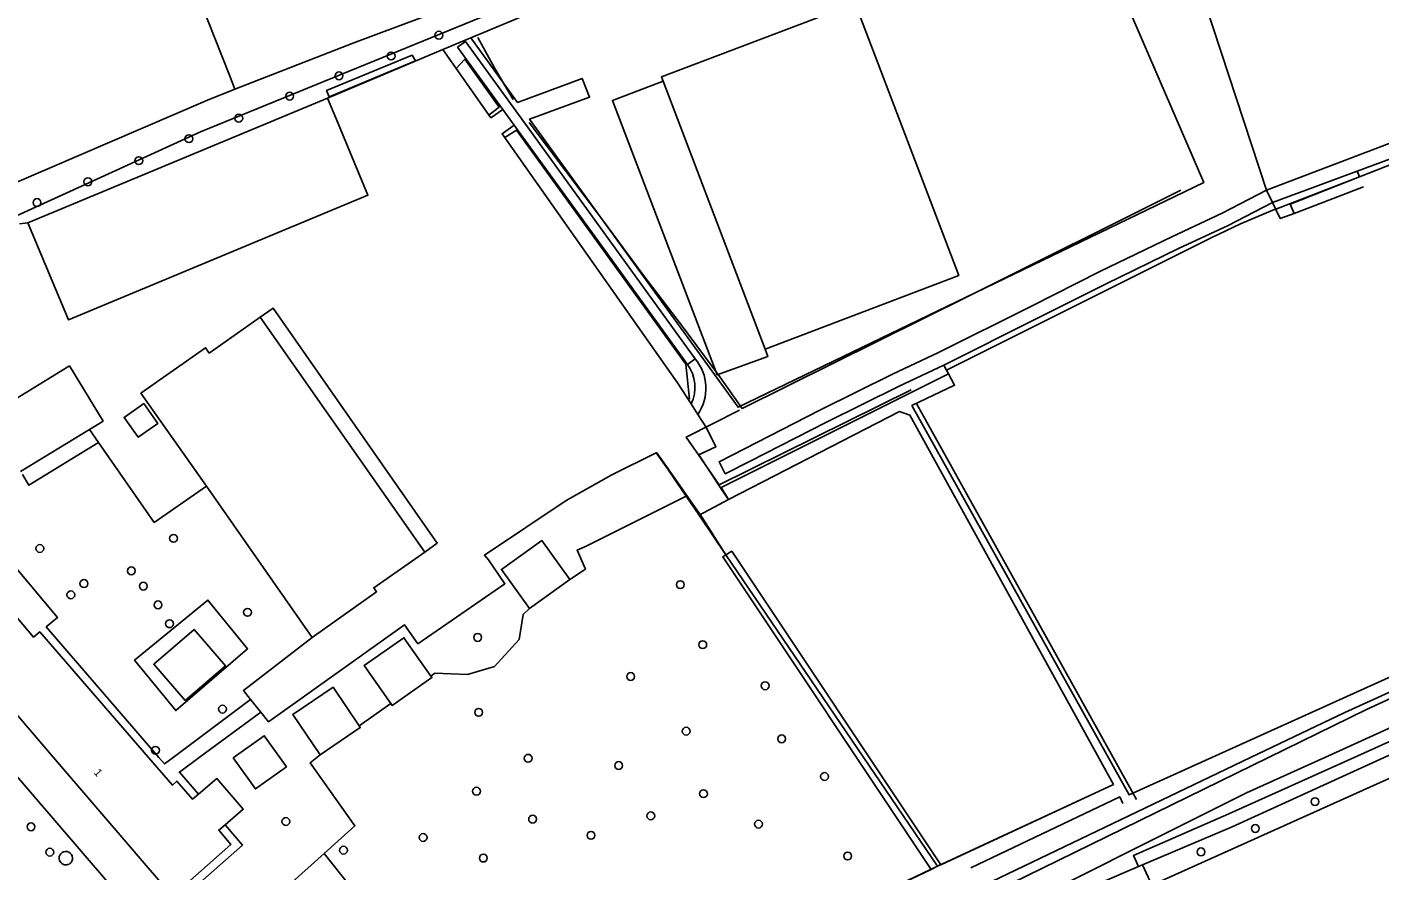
# Model space of a CAD drawing. Extents: x 160203 to 161526, y 379529 to 381797.
# Drawn here: x 161056.6 to 161225.7, y 381235.8 to 381341.3 of the extents above; entities that cross this region are included whole.
import ezdxf

# ---------------------------------------------------------------- set-up
doc = ezdxf.new("R2010")
doc.units = 0
for name, color, linetype in [('IMGEO_Boom', 7, 'Continuous'), ('IMGEO_Bouwland', 7, 'Continuous'), ('IMGEO_Erf', 7, 'Continuous'), ('IMGEO_Grasland_agrarisch', 7, 'Continuous'), ('IMGEO_Grasland_overig', 7, 'Continuous'), ('IMGEO_Groenvoorziening', 7, 'Continuous'), ('IMGEO_Haag', 7, 'Continuous'), ('IMGEO_Hek', 7, 'Continuous'), ('IMGEO_Loofbos', 7, 'Continuous'), ('IMGEO_Open_loods', 7, 'Continuous'), ('IMGEO_Opslagtank', 7, 'Continuous'), ('IMGEO_Pand', 7, 'Continuous'), ('IMGEO_Pand_nummerreeks', 7, 'Continuous'), ('IMGEO_Pand_vergunning_verleend', 7, 'Continuous'), ('IMGEO_Rijbaan_lokaal_gesloten', 7, 'Continuous'), ('IMGEO_Rijbaan_lokaal_halfverhard', 7, 'Continuous'), ('IMGEO_Rijbaan_lokaal_open', 7, 'Continuous'), ('IMGEO_Terreindeel_open', 7, 'Continuous'), ('IMGEO_Voetpad_onverhard', 7, 'Continuous'), ('IMGEO_Waterloop', 7, 'Continuous')]:
    doc.layers.add(name, color=color, linetype=linetype)

msp = doc.modelspace()

# ---------------------------------------------------------------- linework, layer by layer
at = {"layer": 'IMGEO_Boom'}
for centre in [(161108.08, 381340.25), (161102.12, 381337.65), (161095.61, 381335.18), (161089.44, 381332.64), (161083.08, 381329.88), (161076.85, 381327.32), (161070.59, 381324.57), (161064.23, 381321.94), (161057.87, 381319.34), (161074.93, 381277.38), (161058.22, 381276.11), (161069.65, 381273.32), (161063.73, 381271.73), (161071.16, 381271.41), (161138.26, 381271.6), (161062.1, 381270.32), (161072.99, 381269.07), (161084.18, 381268.14), (161074.43, 381266.71), (161112.94, 381265), (161141.06, 381264.09), (161132.05, 381260.11), (161148.86, 381258.96), (161081.05, 381256.04), (161113.06, 381255.64), (161138.99, 381253.28), (161150.93, 381252.33), (161072.67, 381250.89), (161119.24, 381249.9), (161130.55, 381248.99), (161156.28, 381247.62), (161112.79, 381245.78), (161141.15, 381245.47), (161217.57, 381244.48), (161088.97, 381242), (161119.8, 381242.29), (161134.57, 381242.7), (161148.03, 381241.67), (161057.12, 381241.34), (161106.12, 381240), (161127.1, 381240.27), (161210.12, 381241.13), (161096.17, 381238.41), (161059.47, 381238.16), (161113.64, 381237.43), (161159.17, 381237.69), (161203.32, 381238.2)]:
    msp.add_circle(centre, 0.489, dxfattribs=at)
at = {"layer": 'IMGEO_Bouwland'}
for points in [[(161112.08, 381339.93), (161123.08, 381344.5), (161184.52, 381366.19)], [(161184.52, 381366.19), (161203.67, 381321.85), (161145.48, 381293.77), (161119.43, 381329.78), (161126.93, 381332.52), (161125.99, 381334.85), (161117.92, 381331.86), (161112.08, 381339.93)], [(161136.11, 381334.49), (161129.77, 381332.1), (161142.87, 381297.82), (161149.18, 381300.1), (161148.85, 381301.02)]]:
    msp.add_lwpolyline(points, dxfattribs=at)
at = {"layer": 'IMGEO_Erf'}
for points in [[(161065.57, 381289.34), (161072.53, 381279.38), (161079.03, 381283.91)], [(161084.55, 381257.25), (161074.88, 381250), (161073.81, 381249.19), (161073.11, 381250), (161059.03, 381266.32), (161060.41, 381267.49), (161053.4, 381275.9), (161052.82, 381276.6)], [(161092.25, 381265), (161083.66, 381258.35), (161084.55, 381257.25)], [(161084.55, 381257.25), (161085.82, 381255.66)]]:
    msp.add_lwpolyline(points, dxfattribs=at)
at = {"layer": 'IMGEO_Grasland_agrarisch'}
for points in [[(161300.42, 381292.52), (161377.22, 381326.32), (161379.59, 381328.48), (161381.46, 381331.14), (161382.56, 381334.21), (161382.85, 381337.29), (161360.06, 381376.34), (161223.13, 381322.55)], [(161171.51, 381298.41), (161204.59, 381314.93), (161208.28, 381316.67), (161212.29, 381318.38), (161212.66, 381318.52), (161223.13, 381322.55)], [(161171.79, 381297.92), (161171.51, 381298.41)], [(161124.44, 381272.23), (161126.4, 381273.53), (161125.38, 381275.91), (161126.59, 381276.43), (161138.99, 381282.66)], [(161138.99, 381282.66), (161140.6, 381280.28)], [(161140.6, 381280.28), (161144.26, 381282.23)], [(161140.6, 381280.28), (161143.96, 381275.34)], [(161107.07, 381260.17), (161107.58, 381260.53), (161111.67, 381260.36), (161115.03, 381261.35), (161118.13, 381264.76), (161118.64, 381267.85), (161119.41, 381268.62)], [(161098.13, 381253.95), (161102.09, 381256.74)], [(161093.77, 381238.02), (161097.59, 381241.44), (161092, 381249.32), (161093.26, 381250.34)], [(161079.94, 381192.47), (161084.34, 381200.96), (161079.74, 381206.3), (161075.58, 381212.66), (161074.91, 381214.56), (161075.03, 381217.51), (161076.07, 381220.93), (161076.55, 381222.59), (161093.77, 381238.02)], [(161100.9, 381232.41), (161097.9, 381232.77), (161093.77, 381238.02)]]:
    msp.add_lwpolyline(points, dxfattribs=at)
at = {"layer": 'IMGEO_Grasland_overig'}
for points in [[(161367.83, 381310.71), (161294.02, 381278.51), (161294.05, 381277.58), (161293.85, 381277.49), (161232.69, 381250), (161197.17, 381234.04)], [(161143.29, 381283.7), (161171.79, 381297.92)], [(161171.79, 381297.92), (161172.53, 381296.53), (161167.2, 381293.97), (161194.33, 381245.33), (161238.8, 381265.4), (161245.65, 381268.42)], [(161170.8, 381236.6), (161192.37, 381246.64), (161166.94, 381292.77), (161165.65, 381293.23), (161144.26, 381282.23)], [(161144.26, 381282.23), (161143.29, 381283.7)], [(161120.28, 381207.29), (161121.7, 381208.28), (161128, 381211.79), (161128.95, 381212.25), (161140.38, 381217.39), (161157.67, 381225.4), (161171.71, 381231.9), (161176.13, 381234.01), (161209.5, 381250), (161221.3, 381255.61), (161240.99, 381264.56), (161246.29, 381266.89)], [(161118.36, 381211.58), (161155.67, 381229.38), (161169.59, 381236.02)], [(161195.51, 381236.36), (161190.76, 381234.35), (161191.89, 381232.05)], [(161197.17, 381234.04), (161196.03, 381236.58)]]:
    msp.add_lwpolyline(points, dxfattribs=at)
at = {"layer": 'IMGEO_Groenvoorziening'}
for points in [[(161108.58, 381338.47), (161112.08, 381339.93)], [(161094.18, 381332.4), (161108.58, 381338.47)], [(161108.58, 381338.47), (161114.59, 381329.93), (161116.09, 381330.96)], [(161223.13, 381322.55), (161222.84, 381323.27)], [(161055.69, 381316.68), (161056.74, 381316.8)], [(161085.77, 381305.02), (161087.37, 381306.16), (161107.88, 381276.78), (161106.35, 381275.65)], [(161171.51, 381298.41), (161171.17, 381299.03)], [(161140.45, 381292.87), (161141.54, 381291.18), (161142.69, 381288.81), (161140.56, 381287.82), (161143.06, 381284.04), (161143.29, 381283.7)], [(161085.82, 381255.66), (161086.81, 381254.46), (161103.78, 381266.59), (161105.46, 381264.2), (161116.35, 381271.71), (161114.27, 381274.7), (161113.8, 381275.27), (161123.98, 381282.12), (161129.69, 381285.3), (161135.26, 381288.05), (161136.7, 381286.03), (161138.54, 381283.33), (161138.99, 381282.66)], [(161085.82, 381255.66), (161078.13, 381250), (161075.67, 381248.18), (161078.04, 381245.4)], [(161081.37, 381241.6), (161083.54, 381239.04), (161074.73, 381231.27), (161073.02, 381233.25), (161069.95, 381230.62), (161054, 381249.19)]]:
    msp.add_lwpolyline(points, dxfattribs=at)
for start, end in [(154.3838, 333.5556), (333.7104, 154.229)]:
    msp.add_arc((161061.47, 381237.41), 0.839, start, end, dxfattribs=at)
at = {"layer": 'IMGEO_Haag'}
for points in [[(161143.96, 381275.34), (161143.56, 381275.09), (161169.59, 381236.02)], [(161170.8, 381236.6), (161144.68, 381275.77), (161143.96, 381275.34)], [(161169.59, 381236.02), (161170.4, 381236.41), (161170.8, 381236.6)]]:
    msp.add_lwpolyline(points, dxfattribs=at)
at = {"layer": 'IMGEO_Hek'}
for points in [[(161300.42, 381292.52), (161377.22, 381326.32), (161379.59, 381328.48), (161381.46, 381331.14), (161382.56, 381334.21), (161382.85, 381337.29), (161360.06, 381376.34), (161223.13, 381322.55)], [(161194.43, 381372.92), (161211.51, 381320.89)], [(161117.36, 381332.22), (161115.09, 381336.08), (161112.95, 381339.98)], [(161114.38, 381330.3), (161115.63, 381331.27), (161111.35, 381337.26), (161110.21, 381336.06)], [(161139.41, 381294.79), (161138.95, 381299.13), (161117.78, 381328.4), (161116.33, 381327.48)], [(161200.82, 381320.88), (161174.28, 381307.65), (161145.97, 381293.6), (161143.18, 381297.56), (161138.39, 381304), (161133.59, 381310.36), (161128.68, 381317.02), (161119.35, 381329.35)], [(161223.13, 381322.55), (161214.45, 381319.14), (161214.96, 381317.99)], [(161212.25, 381319.36), (161211.51, 381320.89)], [(161223.65, 381321.31), (161214.96, 381317.99)], [(161214.96, 381317.99), (161213.23, 381317.33), (161212.25, 381319.36)], [(161143.13, 381284.08), (161167.09, 381295.92)], [(161143.13, 381284.08), (161140.54, 381287.81), (161139.01, 381290.03), (161145.65, 381293.41)], [(161144.26, 381282.23), (161165.65, 381293.23), (161166.94, 381292.77), (161192.37, 381246.64), (161170.4, 381236.41)], [(161195.28, 381244.76), (161167.83, 381294.15)], [(161140.98, 381279.97), (161136.73, 381286.05), (161135.32, 381288.08), (161135.26, 381288.05), (161129.69, 381285.3), (161123.98, 381282.12), (161113.8, 381275.27)], [(161140.54, 381287.81), (161142.69, 381288.81)], [(161143.32, 381283.81), (161144.26, 381282.23)], [(161140.98, 381279.97), (161143.96, 381275.34), (161170.4, 381236.41)], [(161174.55, 381236.22), (161193.18, 381245.08), (161193.57, 381244.26)], [(161170.4, 381236.41), (161155.67, 381229.38)]]:
    msp.add_lwpolyline(points, dxfattribs=at)
at = {"layer": 'IMGEO_Loofbos'}
for points in [[(161082.6, 381333.52), (161081.92, 381335.28), (161064.56, 381379.14)], [(161211.51, 381320.89), (161194.43, 381372.92)], [(161117.51, 381329), (161115.99, 381327.94), (161137.89, 381296.83), (161139.6, 381294.18)]]:
    msp.add_lwpolyline(points, dxfattribs=at)
at = {"layer": 'IMGEO_Open_loods'}
for points in [[(161056.74, 381316.8), (161094.18, 381332.4)], [(161056.74, 381316.8), (161061.79, 381304.67), (161099.23, 381320.28), (161095.29, 381329.74), (161094.18, 381332.4)]]:
    msp.add_lwpolyline(points, dxfattribs=at)
at = {"layer": 'IMGEO_Opslagtank'}
msp.add_lwpolyline([(161071.21, 381294.22), (161072.95, 381291.75), (161070.51, 381290.02), (161068.76, 381292.49), (161071.21, 381294.22)], dxfattribs=at)
at = {"layer": 'IMGEO_Pand'}
for points in [[(161148.85, 381301.02), (161173.05, 381310.23), (161160.12, 381344.21), (161135.9, 381335.04), (161136.11, 381334.49)], [(161148.85, 381301.02), (161136.11, 381334.49)], [(161079.03, 381283.91), (161070.85, 381295.52), (161078.94, 381301.19), (161079.4, 381300.54), (161085.77, 381305.02)], [(161106.35, 381275.65), (161085.77, 381305.02)], [(161051.6, 381292.62), (161061.91, 381298.93), (161066.13, 381292.03), (161064.42, 381290.98)], [(161055.82, 381285.72), (161064.42, 381290.98)], [(161079.03, 381283.91), (161092.25, 381265)], [(161119.41, 381268.62), (161115.91, 381273.49), (161120.94, 381277.1), (161124.44, 381272.23)], [(161106.35, 381275.65), (161099.95, 381271.21), (161100.31, 381270.71), (161092.25, 381265)], [(161124.44, 381272.23), (161119.41, 381268.62)], [(161081.37, 381241.6), (161080.58, 381240.92), (161082.11, 381239.13), (161074.81, 381232.68), (161059.95, 381250), (161051.4, 381259.95), (161051.8, 381260.26), (161048.63, 381263.95), (161054.29, 381268.75), (161057.43, 381265.04), (161058.22, 381265.7), (161071.8, 381250), (161074.81, 381246.52), (161075.34, 381247.05), (161077.32, 381244.78), (161078.04, 381245.4)], [(161076.38, 381257.1), (161081.42, 381261.46), (161077.49, 381266.01), (161072.45, 381261.65), (161076.38, 381257.1)], [(161102.09, 381256.74), (161098.75, 381261.48), (161103.71, 381264.96), (161107.07, 381260.17)], [(161102.09, 381256.74), (161102.25, 381256.5), (161107.21, 381259.99), (161107.07, 381260.17)], [(161093.26, 381250.34), (161089.85, 381255.38), (161094.86, 381258.77), (161098.13, 381253.95)], [(161082.39, 381249.96), (161086.27, 381252.72), (161088.21, 381250), (161089.04, 381248.84), (161085.16, 381246.07), (161082.39, 381249.96)], [(161093.26, 381250.34), (161098.27, 381253.74), (161098.13, 381253.95)], [(161078.04, 381245.4), (161080.35, 381247.37), (161083.64, 381243.53), (161081.37, 381241.6)]]:
    msp.add_lwpolyline(points, dxfattribs=at)
at = {"layer": 'IMGEO_Pand_vergunning_verleend'}
msp.add_lwpolyline([(161070.05, 381262.15), (161079.22, 381269.66), (161084.19, 381263.58), (161075.2, 381255.85), (161070.05, 381262.15)], dxfattribs=at)
at = {"layer": 'IMGEO_Rijbaan_lokaal_gesloten'}
for points in [[(161108.29, 381192.8), (161114.38, 381197.57), (161123.38, 381204.59), (161125.79, 381205.94), (161175.21, 381228.65), (161209.02, 381245.57), (161218.78, 381250), (161257.16, 381267.43), (161261.42, 381269.36), (161301.19, 381286.35), (161354.19, 381309.33), (161381.5, 381321.67)], [(161255.77, 381270.11), (161236.8, 381261.86), (161224.01, 381256), (161211.76, 381250), (161175.45, 381232.2), (161151.18, 381220.82), (161125.81, 381209.31), (161121.42, 381206.63), (161116.65, 381203.45), (161099.6, 381189.8), (161096.83, 381188), (161094.45, 381187.01), (161091.51, 381186.01)]]:
    msp.add_lwpolyline(points, dxfattribs=at)
at = {"layer": 'IMGEO_Rijbaan_lokaal_halfverhard'}
msp.add_lwpolyline([(161140.45, 381292.87), (161139.6, 381294.18)], dxfattribs=at)
for centre, radius, start, end in [((161135.7, 381296.12), 5.76, 325.5926, 39.9298), ((161135.37, 381296.27), 4.72, 333.639, 36.9761)]:
    msp.add_arc(centre, radius, start, end, dxfattribs=at)
at = {"layer": 'IMGEO_Rijbaan_lokaal_open'}
for points in [[(161116.09, 381330.96), (161110.43, 381338.75), (161111.4, 381339.46), (161119.56, 381328.22), (161129.79, 381314.1), (161140.11, 381299.81)], [(161116.09, 381330.96), (161117.51, 381329)], [(161117.51, 381329), (161118.59, 381327.51), (161128.81, 381313.4), (161139.14, 381299.11)], [(161139.14, 381299.11), (161140.11, 381299.81)]]:
    msp.add_lwpolyline(points, dxfattribs=at)
at = {"layer": 'IMGEO_Terreindeel_open'}
for points in [[(161064.42, 381290.98), (161065.57, 381289.34)], [(161056.05, 381285.34), (161056.86, 381284.02), (161065.57, 381289.34)]]:
    msp.add_lwpolyline(points, dxfattribs=at)
at = {"layer": 'IMGEO_Voetpad_onverhard'}
for points in [[(161096.11, 381384.11), (161098.33, 381382.63), (161110.42, 381352.23), (161110.58, 381351.86), (161110.76, 381351.3), (161110.9, 381350.74), (161110.98, 381350.16), (161111.01, 381349.58), (161110.99, 381348.99), (161110.92, 381348.41), (161110.8, 381347.84), (161110.62, 381347.29), (161110.4, 381346.75), (161110.13, 381346.23), (161108.61, 381343.47), (161097.47, 381339.32), (161082.6, 381333.52)], [(161183.39, 381368.83), (161182.57, 381368.53), (161149.98, 381356.44), (161122.59, 381346.1), (161117.51, 381344.18), (161078.31, 381328.17), (161044.69, 381312.84), (161032.9, 381307.9), (161022.6, 381304.44), (161014.26, 381302.08), (161004.8, 381299.97), (161002.37, 381298.86), (161000.77, 381298.13), (161000, 381297.14), (160999.32, 381295.74)], [(161082.6, 381333.52), (161079.16, 381332.14), (161043.1, 381316.64), (161032.46, 381311.97), (161022.45, 381308.02), (161013.64, 381305.06), (161003.56, 381302.15)]]:
    msp.add_lwpolyline(points, dxfattribs=at)
at = {"layer": 'IMGEO_Waterloop'}
for points in [[(161222.84, 381323.27), (161236, 381328.12), (161256.58, 381336.04), (161274.27, 381343.43), (161317.03, 381359.97), (161360.4, 381377.29), (161368.59, 381365.27), (161375.96, 381351.87), (161383.45, 381338.75), (161383.7, 381336.92), (161383.67, 381335.02), (161383.36, 381333.15), (161382.76, 381331.35), (161381.9, 381329.65), (161380.79, 381328.11), (161379.45, 381326.76), (161377.81, 381325.55), (161367.25, 381320.64), (161353.54, 381314.51), (161316.1, 381298.26), (161316.62, 381297.13)], [(161271.8, 381344.48), (161267.66, 381342.84), (161261.05, 381340.41), (161259.23, 381339.03), (161211.51, 381320.89)], [(161094.39, 381332.57), (161094.06, 381333.33), (161104.76, 381337.75), (161105.17, 381337.05), (161094.39, 381332.57)], [(161195.51, 381236.36), (161194.88, 381237.74), (161206.8, 381242.94), (161222.45, 381250), (161231.6, 381254.13), (161253.42, 381264.34), (161286.37, 381278.95), (161342.74, 381303.34), (161367.3, 381314.56), (161367.99, 381314.88), (161393.64, 381326.61)], [(161222.84, 381323.27), (161212.25, 381319.36), (161206.7, 381316.49), (161200.5, 381313.58), (161191.46, 381309.18), (161182.9, 381304.89), (161171.17, 381299.03)], [(161171.17, 381299.03), (161165.59, 381296.4), (161156.46, 381291.86), (161146.99, 381287.03), (161143.88, 381285.45), (161143.1, 381286.96), (161155.69, 381293.38), (161164.85, 381297.93), (161170.43, 381300.56), (161182.14, 381306.41), (161190.7, 381310.71), (161199.77, 381315.11), (161205.98, 381318.03), (161211.51, 381320.89)], [(161196.03, 381236.58), (161207.23, 381241.35), (161226.2, 381250), (161253.93, 381262.65), (161318.49, 381290.59), (161324.1, 381293.29), (161367.27, 381312.13)], [(161196.03, 381236.58), (161195.51, 381236.36)]]:
    msp.add_lwpolyline(points, dxfattribs=at)

# ---------------------------------------------------------------- texts
at = {"layer": 'IMGEO_Pand_nummerreeks'}
msp.add_text('1', height=1, rotation=310.6397, dxfattribs=at).set_placement((161064.91, 381248.08))

doc.saveas('drawing.dxf')
